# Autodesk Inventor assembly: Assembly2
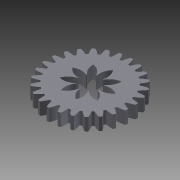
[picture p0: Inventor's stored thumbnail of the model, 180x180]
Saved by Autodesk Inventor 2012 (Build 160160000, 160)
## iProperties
Created: 2018-05
Part Number: Assembly2
Document SubType Name: Assembly
Designer: Elkawokgy
Author: Elkawokgy
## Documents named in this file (3)
- C:\Users\Elkawokgy\Downloads\SpurGearTrials\Assembly2.iam
- C:\Users\Elkawokgy\Downloads\SpurGearTrials\Part1.ipt
- C:\Users\Elkawokgy\Downloads\SpurGearTrials\Spur Gears3.iam
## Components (2 placed, 2 different names)
1. Part1:1
2. Spur Gears:2 [sub-assembly]
